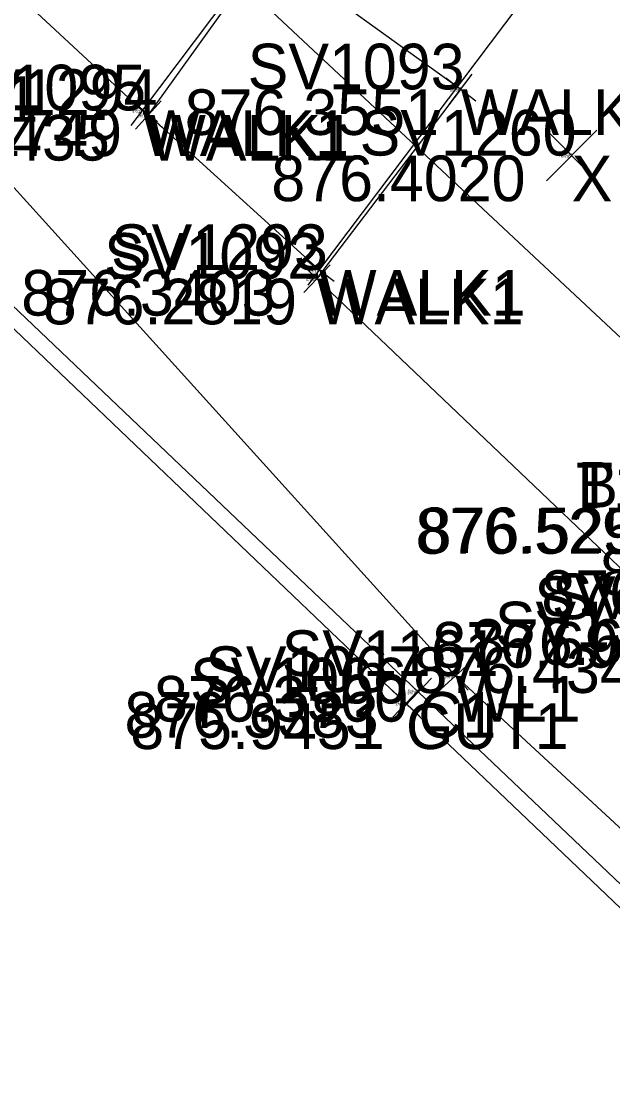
# Model space of a CAD drawing. Extents: x 1469677 to 1493262, y 375219 to 389293.
# Drawn here: x 1480274.04 to 1480289.61, y 379336.98 to 379365.17 of the extents above; entities that cross this region are included whole.
import ezdxf

# ---------------------------------------------------------------- set-up
doc = ezdxf.new("R2010")
doc.units = 0
for name, color, linetype in [('DR_X_Drive_Pipe', 7, 'Continuous'), ('DV_X_Lot_Line', 7, 'Continuous'), ('DV_X_Text', 7, 'Continuous'), ('GK_Visualization', 7, 'Continuous'), ('PNTELEV', 7, 'Continuous'), ('RD_P_Text', 7, 'Continuous'), ('RW_P_Esmt_SW', 7, 'Continuous'), ('RW_P_Esmt_U', 7, 'Continuous'), ('SV_X_Mon_Cells_Found', 7, 'Continuous')]:
    doc.layers.add(name, color=color, linetype=linetype)

msp = doc.modelspace()

# ---------------------------------------------------------------- linework, layer by layer
at = {"layer": 'DR_X_Drive_Pipe'}
msp.add_lwpolyline([(1480172.622, 379452.503), (1480197.813, 379429.111), (1480212.628, 379415.684), (1480231.592, 379398.237), (1480249.493, 379381.828), (1480253.44, 379378.963), (1480259.284, 379374.539), (1480264.171, 379372.865), (1480269.434, 379369.248), (1480270.598, 379368.157), (1480270.755, 379365.904), (1480271.186, 379363.733), (1480285.468, 379347.959), (1480298.848, 379335.614), (1480313.013, 379322.705), (1480330.745, 379305.601), (1480344.344, 379292.312), (1480351.783, 379285.136)], dxfattribs=at)
at = {"layer": 'DV_X_Lot_Line'}
for points in [[(1480355.123, 379297.828), (1480351.285, 379293.6), (1480334.098, 379309.328), (1480328.212, 379315.428), (1480328.737, 379316.329), (1480319.905, 379324.485), (1480307.606, 379335.13), (1480302.895, 379338.359), (1480281.823, 379358.406), (1480285.611, 379363.387), (1480280.441, 379367.109), (1480277.224, 379362.834), (1480260.819, 379378.019), (1480244.572, 379393.153), (1480235.613, 379401.335), (1480215.341, 379421.047), (1480197.466, 379437.463)], [(1480304.825, 379363.469), (1480301.807, 379359.476), (1480289.404, 379368.611), (1480281.88, 379358.636), (1480277.384, 379362.714), (1480284.099, 379372.064), (1480266.845, 379384.676), (1480270.146, 379389.834)]]:
    msp.add_lwpolyline(points, dxfattribs=at)
at = {"layer": 'PNTELEV'}
for p, q in [((1480285.309, 379362.989), (1480285.914, 379363.785)), ((1480285.213, 379363.69), (1480286.009, 379363.085)), ((1480277.525, 379363.234), (1480276.924, 379362.435)), ((1480285.611, 379363.387), (1480285.611, 379363.387)), ((1480277.624, 379362.534), (1480276.825, 379363.135)), ((1480277.755, 379362.378), (1480277.014, 379363.05)), ((1480277.048, 379362.343), (1480277.72, 379363.084)), ((1480277.224, 379362.834), (1480277.224, 379362.834)), ((1480277.384, 379362.714), (1480277.384, 379362.714)), ((1480282.181, 379359.035), (1480281.579, 379358.237)), ((1480282.185, 379358.061), (1480281.461, 379358.75)), ((1480281.478, 379358.043), (1480282.168, 379358.768)), ((1480282.279, 379358.335), (1480281.481, 379358.937)), ((1480281.823, 379358.406), (1480281.823, 379358.406)), ((1480281.88, 379358.636), (1480281.88, 379358.636)), ((1480285.839, 379348.295), (1480285.098, 379347.623)), ((1480285.133, 379348.33), (1480285.804, 379347.588)), ((1480284.131, 379347.881), (1480284.855, 379347.192)), ((1480284.838, 379347.899), (1480284.149, 379347.174)), ((1480285.468, 379347.959), (1480285.468, 379347.959)), ((1480283.806, 379347.582), (1480284.53, 379346.892)), ((1480284.513, 379347.599), (1480283.823, 379346.876)), ((1480284.493, 379347.537), (1480284.493, 379347.537)), ((1480284.168, 379347.237), (1480284.168, 379347.237))]:
    msp.add_line(p, q, dxfattribs=at)
at = {"layer": 'RD_P_Text'}
for points in [[(1480186.975, 379439.363), (1480207.407, 379420.301), (1480210.41, 379417.305), (1480211.712, 379416.16), (1480212.774, 379415.29), (1480213.67, 379414.243), (1480215.361, 379412.945), (1480216.632, 379411.517), (1480217.745, 379410.456), (1480218.76, 379409.536), (1480221.908, 379406.565), (1480233.156, 379396.15), (1480249.934, 379380.311), (1480262.014, 379368.886), (1480262.346, 379369.254), (1480264.513, 379367.165), (1480266.627, 379365.06), (1480266.41, 379364.736), (1480284.493, 379347.537), (1480298.919, 379333.838), (1480300.736, 379332.585), (1480315.855, 379318.308), (1480323.784, 379310.749)], [(1480186.493, 379438.955), (1480206.919, 379419.855), (1480210.187, 379416.932), (1480211.433, 379415.804), (1480213.11, 379414.171), (1480218.471, 379409.217), (1480217.005, 379410.473), (1480215.222, 379412.175), (1480221.495, 379406.235), (1480232.955, 379395.538), (1480249.633, 379380.044), (1480261.648, 379368.645), (1480263.97, 379366.423), (1480266.337, 379364.241), (1480284.168, 379347.237), (1480298.679, 379333.414), (1480300.396, 379332.229), (1480315.326, 379318.045), (1480323.87, 379309.98), (1480343.087, 379291.663), (1480360.248, 379275.585)]]:
    msp.add_lwpolyline(points, dxfattribs=at)
at = {"layer": 'RW_P_Esmt_U'}
for p, q in [((1480287.864, 379360.978), (1480289.197, 379362.313)), ((1480287.864, 379362.313), (1480289.197, 379360.978))]:
    msp.add_line(p, q, dxfattribs=at)
at = {"layer": 'SV_X_Mon_Cells_Found'}
msp.add_lwpolyline([(1477206.544, 382340.781), (1479657.335, 379947.979), (1480466.338, 379191.878)], dxfattribs=at)

# ---------------------------------------------------------------- texts
at = {"layer": 'DV_X_Text'}
for s, height, p in [('876.3551', 1.2, (1480278.343, 379362.187)), ('876.36', 0.06, (1480285.325, 379363.327)), ('876.2435', 1.2, (1480269.675, 379361.514)), ('876.1749', 1.2, (1480269.997, 379361.634)), ('876.17', 0.06, (1480276.967, 379362.774)), ('876.24', 0.06, (1480277.104, 379362.654)), ('876.4020', 1.2, (1480280.622, 379360.446)), ('876.40', 0.06, (1480288.244, 379361.586)), ('876.3403', 1.2, (1480274.038, 379357.436)), ('876.2819', 1.2, (1480274.605, 379357.206)), ('876.28', 0.06, (1480281.542, 379358.346)), ('876.34', 0.06, (1480281.598, 379358.576)), ('876.5298', 1.2, (1480284.419, 379351.172)), ('876.5252', 1.2, (1480284.474, 379351.189)), ('876.6648', 1.2, (1480289.271, 379350.082)), ('876.8433', 1.2, (1480287.732, 379349.538)), ('876.6974', 1.2, (1480284.862, 379348.179)), ('876.6385', 1.2, (1480285.881, 379348.252)), ('876.4348', 1.2, (1480284.363, 379347.512)), ('876.3500', 1.2, (1480277.532, 379346.759)), ('876.35', 0.06, (1480285.186, 379347.899)), ('876.3383', 1.2, (1480276.755, 379346.337)), ('876.34', 0.06, (1480284.211, 379347.477)), ('875.9451', 1.2, (1480276.909, 379346.037)), ('875.95', 0.06, (1480283.887, 379347.177))]:
    msp.add_text(s, height=height, dxfattribs=at).set_placement(p)
at = {"layer": 'GK_Visualization'}
for s, p in [('WL1', (1480271.186, 379362.533)), ('WALK1', (1480285.611, 379362.187)), ('WALK1', (1480277.224, 379361.634)), ('WALK1', (1480277.384, 379361.514)), ('X', (1480288.531, 379360.446)), ('WALK1', (1480281.823, 379357.206)), ('WALK1', (1480281.88, 379357.436)), ('WL1', (1480285.468, 379346.759)), ('C1', (1480284.493, 379346.337)), ('GUT1', (1480284.168, 379346.037))]:
    msp.add_text(s, height=1.2, dxfattribs=at).set_placement(p)
at = {"layer": 'RW_P_Esmt_SW'}
for s, height, p in [('SV1093', 1.2, (1480280, 379363.387)), ('SV1095', 1.2, (1480271.613, 379362.834)), ('SV1294', 1.2, (1480271.914, 379362.714)), ('SV1093', 0.06, (1480285.33, 379363.387)), ('SV1095', 0.06, (1480276.943, 379362.834)), ('SV1294', 0.06, (1480277.111, 379362.714)), ('SV1260', 1.2, (1480282.947, 379361.646)), ('SV1260', 0.06, (1480288.252, 379361.646)), ('SV1293', 1.2, (1480276.4, 379358.636)), ('SV1092', 1.2, (1480276.221, 379358.406)), ('SV1293', 0.06, (1480281.606, 379358.636)), ('SV1092', 0.06, (1480281.543, 379358.406)), ('B102', 1.2, (1480288.68, 379352.389)), ('T102', 1.2, (1480288.643, 379352.372)), ('SV1313', 1.2, (1480287.546, 379349.379)), ('SV1303', 1.2, (1480288.007, 379349.452)), ('SV1302', 1.2, (1480286.508, 379348.712)), ('SV1161', 1.2, (1480280.894, 379347.959)), ('SV1067', 1.2, (1480278.882, 379347.537)), ('SV1066', 1.2, (1480278.481, 379347.237)), ('SV1161', 0.06, (1480285.239, 379347.959)), ('SV1067', 0.06, (1480284.212, 379347.537)), ('SV1066', 0.06, (1480283.884, 379347.237))]:
    msp.add_text(s, height=height, dxfattribs=at).set_placement(p)

doc.saveas('drawing.dxf')
